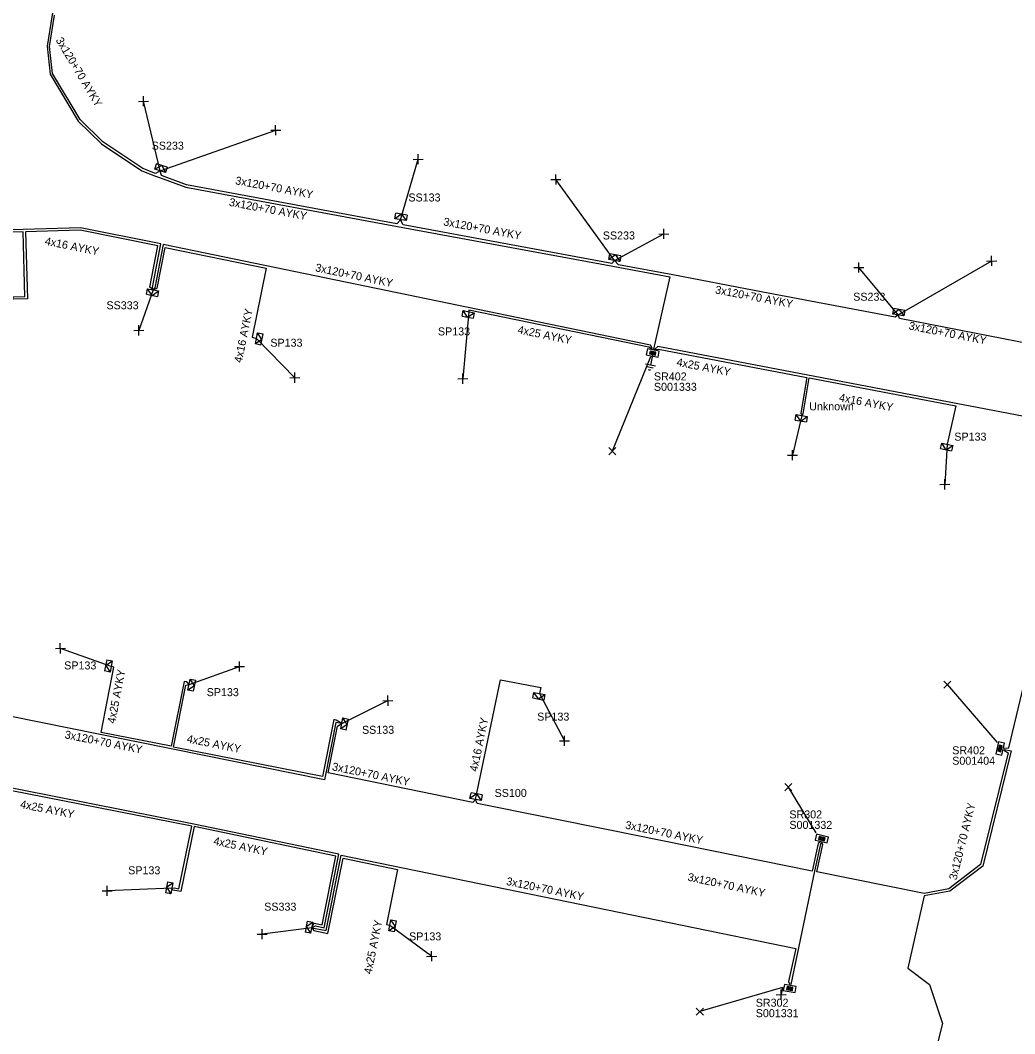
# Model space of a CAD drawing. Extents: x -762500 to -761285, y -1155006 to -1154135.
# Drawn here: x -762054.2 to -761930.7, y -1154659.6 to -1154533.7 of the extents above; entities that cross this region are included whole.
import ezdxf

# ---------------------------------------------------------------- set-up
doc = ezdxf.new("R2010")
doc.units = 0
for name, color, linetype in [('Vrstva 15', 7, 'Continuous'), ('Vrstva 28', 7, 'Continuous'), ('Vrstva 29', 7, 'Continuous'), ('Vrstva 30', 7, 'Continuous'), ('Vrstva 31', 7, 'Continuous'), ('Vrstva 33', 7, 'Continuous'), ('Vrstva 34', 7, 'Continuous'), ('Vrstva 5', 7, 'Continuous'), ('Vrstva 59', 7, 'Continuous'), ('Vrstva 6', 7, 'Continuous')]:
    doc.layers.add(name, color=color, linetype=linetype)

msp = doc.modelspace()

# ---------------------------------------------------------------- linework, layer by layer
at = {"layer": 'Vrstva 15'}
for points in [[(-761975.708, -1154575.339), (-761975.947, -1154576.566)], [(-761975.333, -1154576.685), (-761976.56, -1154576.447)], [(-761975.629, -1154576.944), (-761976.402, -1154576.793)], [(-761976.066, -1154577.18), (-761976.192, -1154577.155)], [(-761975.936, -1154577.205), (-761976.066, -1154577.18)]]:
    msp.add_lwpolyline(points, dxfattribs=at)
at = {"layer": 'Vrstva 28'}
for points in [[(-761976.324, -1154574.564), (-761976.467, -1154575.3)], [(-761976.467, -1154575.3), (-761974.994, -1154575.586)], [(-761974.851, -1154574.85), (-761976.324, -1154574.564)], [(-761975.993, -1154574.815), (-761976.066, -1154575.186)], [(-761976.066, -1154575.186), (-761975.335, -1154575.328)], [(-761975.956, -1154574.87), (-761976.01, -1154575.148)], [(-761976.01, -1154575.148), (-761975.372, -1154575.272)], [(-761975.263, -1154574.957), (-761975.993, -1154574.815)], [(-761975.318, -1154574.994), (-761975.956, -1154574.87)], [(-761975.919, -1154574.925), (-761975.955, -1154575.111)], [(-761975.955, -1154575.111), (-761975.41, -1154575.217)], [(-761975.374, -1154575.031), (-761975.919, -1154574.925)], [(-761975.881, -1154574.981), (-761975.899, -1154575.073)], [(-761975.899, -1154575.073), (-761975.447, -1154575.161)], [(-761975.429, -1154575.069), (-761975.881, -1154574.981)], [(-761975.85, -1154575.035), (-761975.479, -1154575.107)], [(-761975.447, -1154575.161), (-761975.429, -1154575.069)], [(-761975.41, -1154575.217), (-761975.374, -1154575.031)], [(-761975.372, -1154575.272), (-761975.318, -1154574.994)], [(-761975.335, -1154575.328), (-761975.263, -1154574.957)], [(-761974.994, -1154575.586), (-761974.851, -1154574.85)], [(-761932.709, -1154623.373), (-761933.046, -1154624.835)], [(-761931.978, -1154623.542), (-761932.709, -1154623.373)], [(-761932.315, -1154625.003), (-761931.978, -1154623.542)], [(-761933.046, -1154624.835), (-761932.315, -1154625.003)], [(-761932.608, -1154623.778), (-761932.776, -1154624.503)], [(-761932.776, -1154624.503), (-761932.407, -1154624.588)], [(-761932.573, -1154623.835), (-761932.719, -1154624.468)], [(-761932.719, -1154624.468), (-761932.443, -1154624.532)], [(-761932.537, -1154623.891), (-761932.662, -1154624.432)], [(-761932.662, -1154624.432), (-761932.478, -1154624.475)], [(-761932.24, -1154623.863), (-761932.608, -1154623.778)], [(-761932.502, -1154623.948), (-761932.606, -1154624.397)], [(-761932.606, -1154624.397), (-761932.514, -1154624.418)], [(-761932.297, -1154623.899), (-761932.573, -1154623.835)], [(-761932.465, -1154623.999), (-761932.55, -1154624.367)], [(-761932.353, -1154623.934), (-761932.537, -1154623.891)], [(-761932.514, -1154624.418), (-761932.41, -1154623.969)], [(-761932.41, -1154623.969), (-761932.502, -1154623.948)], [(-761932.478, -1154624.475), (-761932.353, -1154623.934)], [(-761932.443, -1154624.532), (-761932.297, -1154623.899)], [(-761932.407, -1154624.588), (-761932.24, -1154623.863)], [(-761955.304, -1154634.853), (-761955.473, -1154635.584)], [(-761953.843, -1154635.191), (-761955.304, -1154634.853)], [(-761955.473, -1154635.584), (-761954.012, -1154635.921)], [(-761954.973, -1154635.124), (-761955.058, -1154635.492)], [(-761955.058, -1154635.492), (-761954.333, -1154635.659)], [(-761954.938, -1154635.18), (-761955.001, -1154635.457)], [(-761955.001, -1154635.457), (-761954.368, -1154635.603)], [(-761954.248, -1154635.291), (-761954.973, -1154635.124)], [(-761954.902, -1154635.237), (-761954.945, -1154635.421)], [(-761954.945, -1154635.421), (-761954.404, -1154635.546)], [(-761954.305, -1154635.326), (-761954.938, -1154635.18)], [(-761954.361, -1154635.362), (-761954.902, -1154635.237)], [(-761954.867, -1154635.294), (-761954.888, -1154635.386)], [(-761954.888, -1154635.386), (-761954.439, -1154635.489)], [(-761954.418, -1154635.397), (-761954.867, -1154635.294)], [(-761954.469, -1154635.434), (-761954.837, -1154635.349)], [(-761954.439, -1154635.489), (-761954.418, -1154635.397)], [(-761954.404, -1154635.546), (-761954.361, -1154635.362)], [(-761954.368, -1154635.603), (-761954.305, -1154635.326)], [(-761954.333, -1154635.659), (-761954.248, -1154635.291)], [(-761954.012, -1154635.921), (-761953.843, -1154635.191)], [(-761959.316, -1154653.497), (-761959.447, -1154654.236)], [(-761957.839, -1154653.757), (-761959.316, -1154653.497)], [(-761958.982, -1154653.742), (-761959.047, -1154654.114)], [(-761958.943, -1154653.797), (-761958.993, -1154654.076)], [(-761958.249, -1154653.871), (-761958.982, -1154653.742)], [(-761958.304, -1154653.909), (-761958.943, -1154653.797)], [(-761957.969, -1154654.496), (-761957.839, -1154653.757)], [(-761959.447, -1154654.236), (-761957.969, -1154654.496)], [(-761959.047, -1154654.114), (-761958.314, -1154654.243)], [(-761958.993, -1154654.076), (-761958.353, -1154654.189)], [(-761958.905, -1154653.851), (-761958.938, -1154654.037)], [(-761958.938, -1154654.037), (-761958.391, -1154654.134)], [(-761958.358, -1154653.948), (-761958.905, -1154653.851)], [(-761958.867, -1154653.906), (-761958.883, -1154653.999)], [(-761958.883, -1154653.999), (-761958.429, -1154654.079)], [(-761958.413, -1154653.986), (-761958.867, -1154653.906)], [(-761958.834, -1154653.96), (-761958.462, -1154654.025)], [(-761958.429, -1154654.079), (-761958.413, -1154653.986)], [(-761958.391, -1154654.134), (-761958.358, -1154653.948)], [(-761958.353, -1154654.189), (-761958.304, -1154653.909)], [(-761958.314, -1154654.243), (-761958.249, -1154653.871)]]:
    msp.add_lwpolyline(points, dxfattribs=at)
at = {"layer": 'Vrstva 31'}
for points in [[(-762035.975, -1154551.992), (-762036.191, -1154552.657), (-762037.523, -1154552.225), (-762037.307, -1154551.559)], [(-762036.641, -1154551.775), (-762037.523, -1154552.225)], [(-762035.975, -1154551.992), (-762037.307, -1154551.559)], [(-762036.641, -1154551.775), (-762036.191, -1154552.657)], [(-762006.186, -1154557.932), (-762006.307, -1154558.621), (-762007.686, -1154558.378), (-762007.565, -1154557.689)], [(-762006.875, -1154557.811), (-762007.686, -1154558.378)], [(-762006.186, -1154557.932), (-762007.565, -1154557.689)], [(-762006.875, -1154557.811), (-762006.307, -1154558.621)], [(-761979.616, -1154562.992), (-761979.737, -1154563.681), (-761981.116, -1154563.438), (-761980.994, -1154562.749)], [(-761980.305, -1154562.87), (-761981.116, -1154563.438)], [(-761979.616, -1154562.992), (-761980.994, -1154562.749)], [(-761980.305, -1154562.87), (-761979.737, -1154563.681)], [(-762038.553, -1154567.773), (-762038.42, -1154567.086), (-762037.046, -1154567.353), (-762037.179, -1154568.041)], [(-762038.553, -1154567.773), (-762037.179, -1154568.041)], [(-762037.866, -1154567.907), (-762038.42, -1154567.086)], [(-762037.866, -1154567.907), (-762037.046, -1154567.353)], [(-761999.354, -1154570.484), (-761999.22, -1154569.797), (-761997.846, -1154570.064), (-761997.98, -1154570.751)], [(-761999.354, -1154570.484), (-761997.98, -1154570.751)], [(-761998.667, -1154570.617), (-761999.22, -1154569.797)], [(-761998.667, -1154570.617), (-761997.846, -1154570.064)], [(-761944.356, -1154569.773), (-761944.478, -1154570.462), (-761945.857, -1154570.219), (-761945.735, -1154569.529)], [(-761945.046, -1154569.651), (-761945.857, -1154570.219)], [(-761944.356, -1154569.773), (-761945.735, -1154569.529)], [(-761945.046, -1154569.651), (-761944.478, -1154570.462)], [(-762024.347, -1154574.074), (-762025.034, -1154573.94), (-762024.767, -1154572.566), (-762024.08, -1154572.699)], [(-762024.213, -1154573.386), (-762024.767, -1154572.566)], [(-762024.347, -1154574.074), (-762024.08, -1154572.699)], [(-762024.213, -1154573.386), (-762025.034, -1154573.94)], [(-761957.954, -1154583.411), (-761957.844, -1154582.72), (-761956.461, -1154582.939), (-761956.571, -1154583.63)], [(-761957.262, -1154583.521), (-761957.844, -1154582.72)], [(-761957.262, -1154583.521), (-761956.461, -1154582.939)], [(-761957.954, -1154583.411), (-761956.571, -1154583.63)], [(-761939.913, -1154586.929), (-761939.768, -1154586.244), (-761938.399, -1154586.535), (-761938.544, -1154587.22)], [(-761939.913, -1154586.929), (-761938.544, -1154587.22)], [(-761939.229, -1154587.074), (-761939.768, -1154586.244)], [(-761939.229, -1154587.074), (-761938.399, -1154586.535)], [(-762043.494, -1154613.186), (-762043.761, -1154614.56)], [(-762043.494, -1154613.186), (-762042.807, -1154613.32), (-762043.074, -1154614.694), (-762043.761, -1154614.56)], [(-762043.627, -1154613.873), (-762042.807, -1154613.32)], [(-762043.627, -1154613.873), (-762043.074, -1154614.694)], [(-762032.731, -1154617.083), (-762033.416, -1154616.938), (-762033.125, -1154615.568), (-762032.44, -1154615.714)], [(-762032.586, -1154616.398), (-762033.125, -1154615.568)], [(-762032.731, -1154617.083), (-762032.44, -1154615.714)], [(-762032.586, -1154616.398), (-762033.416, -1154616.938)], [(-761990.564, -1154617.903), (-761990.43, -1154617.216), (-761989.056, -1154617.483), (-761989.19, -1154618.171)], [(-761989.877, -1154618.037), (-761990.43, -1154617.216)], [(-761990.564, -1154617.903), (-761989.19, -1154618.171)], [(-761989.877, -1154618.037), (-761989.056, -1154617.483)], [(-762013.747, -1154621.904), (-762014.434, -1154621.77), (-762014.167, -1154620.396), (-762013.479, -1154620.529)], [(-762013.613, -1154621.217), (-762014.167, -1154620.396)], [(-762013.747, -1154621.904), (-762013.479, -1154620.529)], [(-762013.613, -1154621.217), (-762014.434, -1154621.77)], [(-761996.866, -1154629.967), (-761996.999, -1154630.654), (-761998.374, -1154630.387), (-761998.24, -1154629.7)], [(-761997.553, -1154629.833), (-761998.374, -1154630.387)], [(-761996.866, -1154629.967), (-761998.24, -1154629.7)], [(-761997.553, -1154629.833), (-761996.999, -1154630.654)], [(-762035.968, -1154640.746), (-762036.211, -1154642.125)], [(-762035.968, -1154640.746), (-762035.278, -1154640.868), (-762035.521, -1154642.247), (-762036.211, -1154642.125)], [(-762036.089, -1154641.436), (-762035.278, -1154640.868)], [(-762036.089, -1154641.436), (-762035.521, -1154642.247)], [(-762018.583, -1154645.626), (-762018.85, -1154647)], [(-762018.583, -1154645.626), (-762017.896, -1154645.76), (-762018.163, -1154647.134), (-762018.85, -1154647)], [(-762018.717, -1154646.313), (-762017.896, -1154645.76)], [(-762007.767, -1154646.974), (-762008.454, -1154646.84), (-762008.187, -1154645.466), (-762007.5, -1154645.599)], [(-762007.633, -1154646.286), (-762008.454, -1154646.84)], [(-762007.633, -1154646.286), (-762008.187, -1154645.466)], [(-762007.767, -1154646.974), (-762007.5, -1154645.599)], [(-762018.717, -1154646.313), (-762018.163, -1154647.134)]]:
    msp.add_lwpolyline(points, dxfattribs=at)
at = {"layer": 'Vrstva 34'}
for points in [[(-762039.555, -1154543.801), (-762038.305, -1154543.779)], [(-762038.919, -1154544.415), (-762038.941, -1154543.165)], [(-762022.489, -1154548.005), (-762022.511, -1154546.755)], [(-762023.125, -1154547.391), (-762021.875, -1154547.369)], [(-762004.799, -1154551.625), (-762004.821, -1154550.375)], [(-762005.435, -1154551.011), (-762004.185, -1154550.989)], [(-761987.679, -1154554.125), (-761987.701, -1154552.875)], [(-761988.315, -1154553.511), (-761987.065, -1154553.489)], [(-761974.915, -1154560.281), (-761973.665, -1154560.259)], [(-761974.279, -1154560.895), (-761974.301, -1154559.645)], [(-761933.549, -1154564.255), (-761933.571, -1154563.005)], [(-761950.685, -1154564.461), (-761949.435, -1154564.439)], [(-761950.049, -1154565.075), (-761950.071, -1154563.825)], [(-761934.185, -1154563.641), (-761932.935, -1154563.619)], [(-762039.489, -1154572.875), (-762039.511, -1154571.625)], [(-762040.125, -1154572.261), (-762038.875, -1154572.239)], [(-762020.755, -1154578.141), (-762019.505, -1154578.119)], [(-762020.119, -1154578.755), (-762020.141, -1154577.505)], [(-761999.875, -1154578.261), (-761998.625, -1154578.239)], [(-761999.239, -1154578.875), (-761999.261, -1154577.625)], [(-761981.132, -1154586.808), (-761980.248, -1154587.692)], [(-761981.132, -1154587.692), (-761980.248, -1154586.808)], [(-761958.935, -1154587.761), (-761957.685, -1154587.739)], [(-761958.299, -1154588.375), (-761958.321, -1154587.125)], [(-761939.369, -1154592.005), (-761939.391, -1154590.755)], [(-761940.005, -1154591.391), (-761938.755, -1154591.369)], [(-762049.875, -1154611.761), (-762048.625, -1154611.739)], [(-762049.239, -1154612.375), (-762049.261, -1154611.125)], [(-762026.989, -1154614.625), (-762027.011, -1154613.375)], [(-762027.625, -1154614.011), (-762026.375, -1154613.989)], [(-761939.502, -1154615.808), (-761938.618, -1154616.692)], [(-761939.502, -1154616.692), (-761938.618, -1154615.808)], [(-762009.185, -1154618.261), (-762007.935, -1154618.239)], [(-762008.549, -1154618.875), (-762008.571, -1154617.625)], [(-761987.255, -1154623.261), (-761986.005, -1154623.239)], [(-761986.619, -1154623.875), (-761986.641, -1154622.625)], [(-761959.252, -1154628.558), (-761958.368, -1154629.442)], [(-761959.252, -1154629.442), (-761958.368, -1154628.558)], [(-762043.429, -1154642.505), (-762043.451, -1154641.255)], [(-762044.065, -1154641.891), (-762042.815, -1154641.869)], [(-762024.815, -1154647.261), (-762023.565, -1154647.239)], [(-762024.179, -1154647.875), (-762024.201, -1154646.625)], [(-762003.755, -1154650.011), (-762002.505, -1154649.989)], [(-762003.119, -1154650.625), (-762003.141, -1154649.375)], [(-761960.335, -1154654.781), (-761959.085, -1154654.759)], [(-761959.699, -1154655.395), (-761959.721, -1154654.145)], [(-761970.252, -1154656.438), (-761969.368, -1154657.322)], [(-761970.252, -1154657.322), (-761969.368, -1154656.438)]]:
    msp.add_lwpolyline(points, dxfattribs=at)
at = {"layer": 'Vrstva 5'}
for points in [[(-762034.01, -1154482.9), (-762035.02, -1154482.4), (-762036.97, -1154488.93), (-762041.6, -1154503.18), (-762042.37, -1154507.15), (-762045.75, -1154517.86), (-762047.49, -1154522.53), (-762047.39, -1154523.12), (-762050.26, -1154533.05), (-762050.9, -1154536.96), (-762050.54, -1154540.43), (-762047.05, -1154546.25), (-762044.16, -1154549.07), (-762039.15, -1154552.42), (-762037.43, -1154553.09), (-762036.93, -1154553.25), (-762033.65, -1154554.46), (-762007.36, -1154559.35), (-761980.62, -1154564.29), (-761973.55, -1154565.6), (-761975.57, -1154574.58)], [(-761922.98, -1154575.07), (-761945.03, -1154570.76), (-761945.17, -1154570.34), (-761945.54, -1154570.63), (-761962.84, -1154567.35), (-761973.19, -1154565.36), (-761979.94, -1154564.1), (-761980.43, -1154563.56), (-761980.74, -1154563.96), (-762006.69, -1154559.16), (-762007, -1154558.5), (-762007.47, -1154559.02), (-762033.57, -1154554.17), (-762036.68, -1154553.01), (-762036.86, -1154552.45), (-762037.45, -1154552.76), (-762039.01, -1154552.15), (-762043.97, -1154548.84), (-762046.81, -1154546.07), (-762050.25, -1154540.34), (-762050.6, -1154536.97), (-762049.97, -1154533.11)], [(-762037.73, -1154567.22), (-762037.83, -1154566.91), (-762036.79, -1154561.52), (-762046.77, -1154559.5), (-762073.9, -1154560.28), (-762093.44, -1154565.09), (-762108.37, -1154568.95), (-762127.65, -1154573.67), (-762149.26, -1154579.08), (-762146.38, -1154590.11), (-762144.55, -1154589.61), (-762144.24, -1154589.69)], [(-762037.73, -1154567.22), (-762038.13, -1154566.88), (-762037.14, -1154561.76), (-762046.8, -1154559.8), (-762053.59, -1154560), (-762053.35, -1154568.34), (-762055.06, -1154568.39), (-762055.3, -1154568.25), (-762055.07, -1154568.09), (-762053.66, -1154568.05), (-762053.89, -1154560), (-762073.86, -1154560.58), (-762089.54, -1154564.44), (-762087.57, -1154572.43), (-762086.58, -1154572.19)], [(-761975.69, -1154574.55), (-761975.95, -1154574.08), (-762036.49, -1154561.59), (-762037.53, -1154566.96), (-762037.73, -1154567.22)], [(-762037.73, -1154567.22), (-762037.24, -1154567.02), (-762036.25, -1154561.95), (-762023.68, -1154564.54), (-762025.45, -1154573.08), (-762024.9, -1154573.25)], [(-761975.82, -1154574.53), (-761976.15, -1154574.35), (-761998.51, -1154569.74), (-761998.53, -1154569.93)], [(-761931.99, -1154624.17), (-761931.42, -1154624.12), (-761922.94, -1154588.66), (-761923.49, -1154586.95), (-761924.58, -1154585.24), (-761925.92, -1154584.04), (-761927.8, -1154583.28), (-761975.02, -1154574.25), (-761975.44, -1154574.61)], [(-761975.31, -1154574.63), (-761974.94, -1154574.57), (-761956.52, -1154578.1), (-761957.26, -1154582.54), (-761957.15, -1154582.83)], [(-761957.15, -1154582.83), (-761956.97, -1154582.61), (-761956.22, -1154578.15), (-761938.03, -1154581.64), (-761939.08, -1154586.39)], [(-762014.3, -1154621.08), (-762015.05, -1154620.95), (-762016.45, -1154628.07), (-762035.28, -1154624.27), (-762044.53, -1154622.42), (-762059.09, -1154619.49), (-762063.31, -1154620.47), (-762065.57, -1154611.64), (-762066.07, -1154612.08), (-762065.74, -1154612.2), (-762063.68, -1154620.51), (-762078.48, -1154624.21), (-762097.97, -1154629.2), (-762117.33, -1154634), (-762131.8, -1154637.5), (-762133.25, -1154631.83)], [(-762014.3, -1154621.08), (-762014.98, -1154620.66), (-762015.29, -1154620.61), (-762016.68, -1154627.69), (-762035.21, -1154624.02), (-762033.66, -1154616.32), (-762033.27, -1154616.25), (-762033.54, -1154615.92), (-762033.87, -1154615.85), (-762035.51, -1154623.92), (-762044.18, -1154622.19), (-762042.61, -1154614.11), (-762042.94, -1154614.01)], [(-761997.69, -1154630.52), (-761994.58, -1154615.65), (-761989.57, -1154616.63), (-761989.74, -1154617.35)], [(-761997.69, -1154630.52), (-761998, -1154630.9), (-762015.98, -1154627.23), (-762014.82, -1154621.41), (-762014.3, -1154621.08)], [(-761932.02, -1154624.3), (-761931.15, -1154624.48), (-761934.67, -1154638.79), (-761938.76, -1154641.9), (-761941.96, -1154642.51), (-761943.98, -1154651.48), (-761941.3, -1154653.52), (-761939.67, -1154658.34), (-761950, -1154699), (-761956.83, -1154725.63), (-761957.25, -1154725.68)], [(-761932.05, -1154624.42), (-761931.51, -1154624.73), (-761934.93, -1154638.61), (-761938.88, -1154641.62), (-761941.96, -1154642.2), (-761955.28, -1154639.5), (-761954.52, -1154636.1), (-761954.64, -1154635.9)], [(-762018.03, -1154646.45), (-762017.58, -1154646.23), (-762016.49, -1154646.47), (-762014.67, -1154637.34), (-762032.87, -1154633.54), (-762058.42, -1154628.52), (-762100.97, -1154638.95), (-762109.63, -1154679.98), (-762106.75, -1154684.45), (-762093.8, -1154686.97), (-762093.14, -1154686.59)], [(-762018.03, -1154646.45), (-762017.74, -1154645.89), (-762016.72, -1154646.11), (-762015.02, -1154637.57), (-762032.64, -1154633.9), (-762034.29, -1154641.96), (-762035.28, -1154641.78), (-762035.4, -1154641.56), (-762035.09, -1154641.51), (-762034.53, -1154641.61), (-762032.93, -1154633.85), (-762057.86, -1154628.94), (-762059.66, -1154638.15), (-762059.84, -1154638.32), (-762059.95, -1154638.09), (-762058.14, -1154628.89), (-762058.41, -1154628.83), (-762084.76, -1154635.28), (-762085.35, -1154641.05)], [(-761954.9, -1154635.84), (-761955.1, -1154635.99), (-761955.84, -1154639.44), (-761980.8, -1154634.37), (-761997.46, -1154631.01), (-761997.69, -1154630.52)], [(-761954.77, -1154635.87), (-761955.55, -1154639.44), (-761958.5, -1154653.51)], [(-762018.03, -1154646.45), (-762016.25, -1154646.82), (-762014.38, -1154637.46), (-761957.89, -1154649.03), (-761958.79, -1154653.12), (-761958.63, -1154653.49)], [(-762018.03, -1154646.45), (-762017.77, -1154646.82), (-762016.02, -1154647.18), (-762014.14, -1154637.81), (-762007.37, -1154639.23), (-762008.74, -1154646.06), (-762008.32, -1154646.15)]]:
    msp.add_lwpolyline(points, dxfattribs=at)
at = {"layer": 'Vrstva 59'}
for points in [[(-762036.86, -1154552.44), (-762038.93, -1154543.79)], [(-762036.86, -1154552.45), (-762022.5, -1154547.38)], [(-762007, -1154558.5), (-762004.81, -1154551)], [(-761980.43, -1154563.56), (-761987.69, -1154553.5)], [(-761980.43, -1154563.56), (-761974.29, -1154560.27)], [(-761945.17, -1154570.34), (-761950.06, -1154564.45)], [(-761945.17, -1154570.34), (-761933.56, -1154563.63)], [(-762037.73, -1154567.22), (-762039.5, -1154572.25)], [(-761998.53, -1154569.93), (-761999.25, -1154578.25)], [(-762024.9, -1154573.25), (-762020.13, -1154578.13)], [(-761975.93, -1154575.54), (-761980.69, -1154587.25)], [(-761957.15, -1154582.83), (-761958.31, -1154587.75)], [(-761939.08, -1154586.39), (-761939.38, -1154591.38)], [(-762042.94, -1154614.01), (-762049.25, -1154611.75)], [(-762033.27, -1154616.25), (-762027, -1154614)], [(-761932.85, -1154623.45), (-761939.06, -1154616.25)], [(-762014.3, -1154621.08), (-762008.56, -1154618.25)], [(-761989.74, -1154617.35), (-761986.63, -1154623.25)], [(-761955.38, -1154634.69), (-761958.81, -1154629)], [(-762035.4, -1154641.56), (-762043.44, -1154641.88)], [(-762008.32, -1154646.15), (-762003.13, -1154650)], [(-762018.03, -1154646.45), (-762024.19, -1154647.25)], [(-761959.53, -1154653.9), (-761969.81, -1154656.88)], [(-761959.53, -1154653.9), (-761959.71, -1154654.77)]]:
    msp.add_lwpolyline(points, dxfattribs=at)

# ---------------------------------------------------------------- texts
at = {"layer": 'Vrstva 29'}
for s, p in [('S001333', (-761975.52, -1154579.76)), ('S001404', (-761938.46, -1154626.21)), ('S001332', (-761958.69, -1154634.18)), ('S001331', (-761962.87, -1154657.57))]:
    msp.add_text(s, height=0.9943, dxfattribs=at).set_placement(p)
at = {"layer": 'Vrstva 30'}
for s, p in [('SR402', (-761975.52, -1154578.47)), ('SR402', (-761938.46, -1154624.91)), ('SR302', (-761958.69, -1154632.88)), ('SR302', (-761962.87, -1154656.27))]:
    msp.add_text(s, height=0.9943, dxfattribs=at).set_placement(p)
at = {"layer": 'Vrstva 33'}
for s, p in [('SS233', (-762037.91, -1154549.8)), ('SS133', (-762006.02, -1154556.24)), ('SS233', (-761981.87, -1154560.96)), ('SS233', (-761950.76, -1154568.57)), ('SS333', (-762043.53, -1154569.63)), ('SP133', (-762002.35, -1154572.88)), ('SP133', (-762023.17, -1154574.28)), ('Unknown', (-761956.23, -1154582.19)), ('SP133', (-761938.2, -1154585.95)), ('SP133', (-762048.78, -1154614.37)), ('SP133', (-762031.08, -1154617.69)), ('SP133', (-761990.02, -1154620.73)), ('SS133', (-762011.78, -1154622.37)), ('SS100', (-761995.31, -1154630.21)), ('SP133', (-762040.83, -1154639.82)), ('SS333', (-762023.93, -1154644.34)), ('SP133', (-762005.93, -1154648.03))]:
    msp.add_text(s, height=0.9943, dxfattribs=at).set_placement(p)
at = {"layer": 'Vrstva 6'}
for s, height, rotation, p in [('3x120+70 AYKY', 0.99429, 300.93139, (-762049.87, -1154536.2)), ('3x120+70 AYKY', 0.99428, 349.46387, (-762027.58, -1154554.09)), ('3x120+70 AYKY', 0.99429, 349.46327, (-762028.36, -1154556.77)), ('3x120+70 AYKY', 0.99429, 349.52291, (-762001.73, -1154559.2)), ('4x16 AYKY', 0.9943, 348.56004, (-762051.24, -1154561.6)), ('3x120+70 AYKY', 0.99429, 348.33974, (-762017.65, -1154564.9)), ('3x120+70 AYKY', 0.99429, 349.274, (-761967.97, -1154567.65)), ('4x16 AYKY', 0.9943, 78.34214, (-762026.72, -1154576.34)), ('4x25 AYKY', 0.9943, 348.33974, (-761992.51, -1154572.6)), ('3x120+70 AYKY', 0.99429, 348.9496, (-761943.92, -1154572.13)), ('4x25 AYKY', 0.9943, 349.16512, (-761972.76, -1154576.64)), ('4x16 AYKY', 0.9943, 349.14696, (-761952.58, -1154581.04)), ('4x25 AYKY', 0.9943, 79.01925, (-762042.46, -1154621.16)), ('4x16 AYKY', 0.9943, 78.20142, (-761997.47, -1154627.13)), ('3x120+70 AYKY', 0.99429, 348.67696, (-762048.78, -1154622.91)), ('4x25 AYKY', 0.9943, 348.78642, (-762033.6, -1154623.43)), ('3x120+70 AYKY', 0.99428, 348.45245, (-762015.56, -1154626.88)), ('4x25 AYKY', 0.9943, 348.85728, (-762054.31, -1154631.56)), ('3x120+70 AYKY', 0.99429, 76.13867, (-761937.92, -1154640.6)), ('3x120+70 AYKY', 0.99429, 348.51054, (-761979.14, -1154634.14)), ('4x25 AYKY', 0.9943, 348.20729, (-762030.3, -1154636.12)), ('3x120+70 AYKY', 0.99428, 347.91931, (-761971.39, -1154640.6)), ('3x120+70 AYKY', 0.99429, 348.42467, (-761993.93, -1154641.13)), ('4x25 AYKY', 0.9943, 78.69651, (-762010.6, -1154652.28))]:
    msp.add_text(s, height=height, rotation=rotation, dxfattribs=at).set_placement(p)

doc.saveas('drawing.dxf')
